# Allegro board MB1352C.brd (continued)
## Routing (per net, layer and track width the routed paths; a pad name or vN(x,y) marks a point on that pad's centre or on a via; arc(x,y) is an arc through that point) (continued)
VBUS1: length 21.2
  TOP w0.254: CN7.B4 9.38,15.18 CN7.A9 ; CN7.B9 9.38,17.68 CN7.A4
  TOP w0.356: 21.08,6.99 22.1,5.97 U23.5
  TOP w0.508: R69.2 19.56,10.59 ; R69.2 18.24,8.64 ; R69.2 20.88,8.64 ; R69.2 19.56,6.68 ; 16.38,13.08 v1(17.53,13.08)
  BOTTOM w0.508: v1(18.67,17.4) 20.45,17.4 22.1,19.05 R64.2 ; D6.1 v1(4.19,14.61) ; C16.2 10.67,14.35 9.89,15.13 9.43,15.13 CN7.B4
  vias: v1(17.65,10.67) v1(17.65,9.93) v1(17.65,9.12) v1(17.65,8.26)
VBUS2: length 38.1
  TOP w0.254: CN5.B4 104.92,43.24 CN5.A9 ; CN5.B9 104.92,40.74 CN5.A4
  TOP w0.356: U24.5 44.32,11.94 43.94,12.32 43.31,12.32
  TOP w0.508: 40.33,14.48 R70.2 ; R70.2 41.66,12.52 ; R70.2 42.98,14.48 ; R70.2 41.66,16.43
  L3_SIG w0.508: CN5.B9 104.62,40.79 104.22,40.38 104.22,37.13 104.85,36.5 108.58,36.5 109.22,37.13 109.22,38.94 v1(109.42,39.14)
  BOTTOM w0.508: CN5.B9 104.5,40.79 104.19,41.09 104.19,42.83 104.55,43.19 CN5.B4 ; v1(109.42,39.14) 109.73,39.45 C15.2 D1.1 ; v1(43.03,16.89) 46.86,16.89 50.04,20.07 R63.2
  vias: v1(40.65,16.93) v1(41.42,16.89) v1(42.29,16.89)
VDD: length 105.8
  TOP w0.165: v1(28.45,41.02) 27.69,40.26 U13.1 ; v1(25.4,41.91) 25.4,41.15 25.69,40.86 U13.6
  TOP w0.203: U13.28 27.69,34.03 28.27,33.45 v1(28.52,33.45) ; C51.2 18.2,24.17 U17.10 ; C47.2 95.72,54.19 U16.10 ; v1(23.88,33.53) 24.39,34.04 U13.20
  TOP w0.254: U6.22 v2(66.52,47.24) ; U6.25 v2(65.02,47.24) ; U6.10 66.52,40.89 v2(66.71,40.7) ; U6.13 68.71,42.57 68.96,42.31 68.96,42.16 v1(69.09,42.04) ; U6.26 64.52,47.63 v2(64.9,48.01) ; U6.29 v2(63.02,47.24) ; v1(69.22,45.85) 68.94,45.57 U6.19 ; U6.6 v2(64.52,40.89) ; v3(81.81,41.15) 81.86,41.1 81.86,40.72 U8.H3 ; v2(62.74,40.51) 63.02,40.79 U6.3 ; U8.E4 82.83,42.16 v3(82.89,42.23) ; v2(64.77,40.13) 65.02,40.38 U6.7 ; U8.E3 v3(81.41,42.16) ; U6.32 61.11,45.57 60.71,45.97 ; U6.38 61.09,42.32 61.09,41.53 60.58,41.02 v1(60.33,41.02) ; U8.B2 v3(81.42,43.18)
  TOP w0.508: R8.1 v1(94.74,31.88) ; R24.1 R22.1 v1(56.13,43.05) ; v1(58.67,48.13) C17.1 59.56,47.12 60.71,45.97 ; R21.1 v1(33.05,43.31) ; v1(56.13,44.32) R17.1 R13.1 ; v1(71.63,36.7) 71.63,37.85 C35.1 70.87,37.85 v1(70.87,36.7) ; R28.1 v1(83.31,33.78) ; R51.2 94.23,18.29 v1(94.97,18.29) ; C47.2 96.08,53.4 v1(96.58,53.4) ; v1(19.81,24.77) C51.2
  BOTTOM w0.381: C89.1 81.66,40.77 81.81,40.92 v3(81.81,41.15) ; C80.1 81.42,43.7 v3(81.42,43.18) ; C81.1 80.52,42.16 v3(81.41,42.16) ; C87.1 83.38,42.23 v3(82.89,42.23)
  BOTTOM w0.508: v2(62.74,40.51) 62.48,40.77 C86.1 ; C91.1 25.27,41.78 v1(25.4,41.91) ; v1(73.64,44.05) 72.92,44.05 72.64,44.32 R88.1 R91.1 ; C77.1 65.91,46.35 v2(65.02,47.24) ; v1(93.47,29.34) 93.47,29.97 R9.2 ; v1(28.52,33.45) 28.5,33.45 27.94,34.01 C93.1 ; v1(76.33,43.18) 75.95,43.56 R87.1 ; v2(64.9,48.01) 64.01,47.12 64.01,46.23 63.63,45.85 C78.1 ; C47.2 96.08,53.4 v1(96.58,53.4) ; v1(76.96,36.32) 76.96,37.34 C92.1 75.95,37.34 v1(75.95,36.32) ; v1(69.09,42.04) 69.34,41.78 C82.1 ; 98.3,3.94 CN8.18 ; CN8.18 97.41,4.83 ; CN8.18 98.3,5.72 ; CN8.18 99.19,4.83 ; C75.1 70.48,45.97 69.34,45.97 v1(69.22,45.85) ; C90.1 28.45,40.39 v1(28.45,41.02) ; C83.1 66.9,40.89 v2(66.71,40.7) ; C102.1 96.09,3.68 ; C102.1 95.5,4.31 ; C102.1 94.92,3.68 ; R106.2 v1(81.92,33.78) ; CN9.18 C101.1 v1(39.24,5.84) ; C76.1 68.07,45.69 v2(66.52,47.24) ; C84.1 65.53,40.89 v2(64.77,40.13) ; v2(63.02,47.24) 61.34,45.57 C79.1 ; C88.1 59.44,40.51 59.94,41.02 v1(60.33,41.02) ; R103.1 20.32,36.83 v1(19.68,37.47) 20.32,38.1 R100.1 ; v1(32.26,34.54) 32.18,34.62 32.18,35.38 R108.1 ; C95.1 v1(23.62,32.38) ; v1(19.81,24.77) C51.2 ; R28.1 v1(83.31,33.78) ; v1(30.04,45.66) R90.1 ; R107.2 v1(80.52,33.78) ; v1(23.88,33.53) 22.61,33.53 C94.1 ; C85.1 v2(64.52,40.89) ; R97.1 v1(32.89,40.26) ; R93.1 v1(21.34,42.67)
  vias: v1(89.66,13.59) v1(89.66,12.7) v1(90.55,13.59) v1(90.55,12.7)
1_CC1: length 137.7
  TOP w0.127: SB4.2 87.63,39.75 87.63,38.31 T2.3 v1(87.16,36.62) ; SB21.2 v1(15.75,29.46)
  L3_SIG w0.102: v1(87.16,36.62) 86.66,36.62 86.11,36.07 86.11,32.4 v1(85.09,31.38)
  BOTTOM w0.127: v1(87.16,36.62) 86.7,36.62 84.84,38.48 84.84,45.21 79.76,50.29 48.9,50.29 46.23,47.62 46.23,36.6 42.55,32.92 39.64,32.92 38.45,31.72 34.89,31.72 33.53,30.36 33.53,29.46 32.77,28.7 30.35,28.7 29.08,27.43 20.24,27.43 17.48,30.2 16.48,30.2 v1(15.75,29.46) 16.26,28.96 16.26,25.4 16,25.15 14.99,25.15 14.1,24.26 14.1,20.04 15.75,18.38 15.75,15.11 SB56.2 ; T12.3 86.36,27.56 85.09,28.83 v1(85.09,31.38) 85.12,31.38 D11.2
1_CC2: length 137.8
  TOP w0.127: SB22.2 v1(17.27,29.59) ; T4.3 87.38,27.56 v1(86.11,28.83) 85.98,28.96 D12.2 ; v1(90.81,36.58) 90.81,37.55 T3.3 91.1,40.05 SB5.2
  L3_SIG w0.102: v1(86.11,28.83) 86.61,29.34 86.61,35.69 87,36.07 90.3,36.07 v1(90.81,36.58)
  BOTTOM w0.127: SB57.2 16.32,18.22 16.32,18.35 14.48,20.19 14.48,24 15.11,24.64 16.13,24.64 16.76,25.27 16.76,29.08 v1(17.27,29.59) 17.55,29.59 20.09,27.05 29.34,27.05 30.61,28.32 33.02,28.32 34.04,29.34 34.04,30.33 35.05,31.34 38.61,31.34 39.78,32.51 42.8,32.51 46.74,36.45 46.74,47.37 49.15,49.78 79.63,49.78 84.33,45.09 84.33,38.23 86.49,36.07 90.3,36.07 v1(90.81,36.58)
1_SBU1: length 38.6
  TOP w0.127: v1(13.97,25.02) 14.95,25.02 15.07,24.89 U17.15 ; U13.27 27.29,33.93 29.08,32.13 29.34,32.13 R39.2 29.34,30.86 29.34,28.98 v1(28.7,28.35)
  L3_SIG w0.102: v1(28.7,28.35) 27.53,27.18 22.23,27.18 20.45,25.4 19.43,25.4 18.67,24.64 15.37,24.64 14.73,25.27 14.22,25.27 v1(13.97,25.02) 13.97,24.51 14.35,24.13 14.35,22.61 16,20.95 16,20.09 15.89,19.97 15.89,15.89 v1(14.73,14.73)
  BOTTOM w0.127: SB58.2 13.72,14.73 v1(14.73,14.73)
1_SBU2: length 35.9
  TOP w0.127: U13.26 26.89,33.69 28.16,32.42 28.16,32.02 28.69,31.5 R38.2 28.07,30.86 28.07,28.85 v1(27.69,28.47) ; v1(13.97,25.78) 14.99,25.78 15.47,25.29 U17.14
  L3_SIG w0.102: v1(14.99,17.65) 15.49,18.16 15.49,20.95 13.08,23.37 13.08,24.89 v1(13.97,25.78) 14.86,25.78 15.6,25.04 18.57,25.04 19.3,25.78 20.19,25.78 22.04,27.63 26.84,27.63 v1(27.69,28.47)
  BOTTOM w0.127: SB53.2 v1(14.99,17.65)
2_SBU1: length 27.9
  TOP w0.127: U16.15 99.86,52.88 100.97,51.77 v1(100.97,51.44) 102.36,50.04 SB41.2 ; U8.A5 82.92,44.31 83.82,45.21 83.82,46.1 83.83,46.11 83.83,47.41 84.55,48.13 85.34,48.13 v2(85.47,48.26)
  L3_SIG w0.102: v1(100.97,51.44) 100.84,51.31 99.69,51.31 98.3,49.91 97.03,49.91 96.01,48.9 86.11,48.9 v2(85.47,48.26)
2_SBU2: length 27
  TOP w0.127: U8.A6 84.21,44.95 84.21,47.25 84.71,47.75 85.34,47.75 v2(85.47,47.62) ; U16.14 99.46,52.74 100.33,51.87 100.33,51.31 v1(100.97,50.67) SB42.2
  L3_SIG w0.102: v1(100.97,50.67) 100.71,50.93 99.82,50.93 98.42,49.53 97.16,49.53 96.14,48.51 86.36,48.51 v2(85.47,47.62)
A0: length 4.1
  TOP w0.127: U6.33 60.72,45.07 60.07,45.72 v1(59.69,45.72) 58.8,45.72 R13.2
  BOTTOM w0.127: v1(59.69,45.72) 58.8,45.72 R13.2
A1: length 4.4
  TOP w0.127: R17.2 59.3,44.95 v1(59.69,44.95) 60.21,44.95 60.59,44.57 U6.34
  BOTTOM w0.127: v1(59.69,44.95) 59.3,44.95 R17.2
A2: length 4.1
  TOP w0.127: U6.35 60.58,44.07 59.94,43.43 v1(59.56,43.43) 59.05,43.43 R22.2
  BOTTOM w0.127: R22.2 59.05,43.43 v1(59.56,43.43)
ADDR1: length 6.7
  TOP w0.127: U8.H5 v3(82.92,41.12)
  BOTTOM w0.127: v3(82.92,41.12) 82.92,36.71 R105.2 R104.1
ADDR2: length 9.6
  TOP w0.127: v3(82.96,42.77) 82.85,42.66 U8.D4
  BOTTOM w0.127: R87.2 R86.1 79.76,45.59 80.9,44.45 80.9,43.05 81.18,42.77 v3(82.96,42.77)
AUX_N_1: length 14.7
  TOP w0.13: R12.2 20.13,46.8 19.67,46.8 v2(19.51,46.96) ; U9.1 17.13,41.33 16.65,41.33 v2(16.48,41.49) 16.32,41.33 15.65,41.33 15.16,40.84 14.81,40.84 14.55,41.1 CN6.17
  BOTTOM w0.13: v2(16.48,41.49) 16.65,41.33 16.94,41.33 17.5,41.88 17.5,45.67 18.63,46.8 19.34,46.8 v2(19.51,46.96) 19.67,46.8 20.13,46.8 R12.2
AUX_N_2: length 15.3
  TOP w0.13: v2(68.88,57.56) 68.72,57.72 68.72,58.86 69.04,59.18 CN2.17 ; C14.2 71,51.05 71,52.87 70.49,53.38 70.49,53.91 v2(70.66,54.08) 70.49,54.24 U3.2
  BOTTOM w0.13: R31.1 68.71,59.05 68.71,57.74 v2(68.88,57.56) 68.72,57.39 68.72,56.63 70.49,54.86 70.49,54.24 v2(70.66,54.08)
AUX_P_1: length 14.8
  TOP w0.13: CN6.15 14.52,40.1 14.88,40.46 15.32,40.46 15.81,40.95 16.32,40.95 v2(16.48,40.78) 16.65,40.95 17.13,40.95 U9.2 ; v2(19.51,46.25) 19.67,46.42 20.13,46.42 R11.2
  BOTTOM w0.13: v2(16.48,40.78) 16.65,40.95 17.1,40.95 17.88,41.73 17.88,45.52 18.78,46.42 19.34,46.42 v2(19.51,46.25) 19.67,46.42 20.13,46.42 R11.2
AUX_P_2: length 15.3
  TOP w0.13: CN2.15 68.04,59.17 68.34,58.87 68.34,57.72 v2(68.17,57.56) ; U3.1 69.99,54.99 70.11,54.87 70.11,54.24 v2(69.95,54.08) 70.11,53.91 70.11,53.22 70.62,52.72 70.62,50.93 C13.2
  BOTTOM w0.13: v2(69.95,54.08) 70.11,54.24 70.11,54.7 68.34,56.47 68.34,57.39 v2(68.17,57.56) 68.33,57.71 68.33,59.05 R30.1
C1_CC1: length 32.1
  TOP w0.127: CN7.A5 11.08,17.18 11.3,17.4 v1(14.22,17.4) ; D5.6 16.8,16.57 16.92,16.44 17.33,16.44 v1(17.65,16.76) 17.79,16.9 17.79,17.76 18.03,18 18.03,18.65 17.53,19.16 v1(17.44,19.16) 17.02,19.58 17.02,20.67 16.28,21.41 U17.4
  L3_SIG w0.102: v1(14.73,13.97) 14.22,14.48 v1(14.22,17.4)
  BOTTOM w0.127: 16.51,13 18.16,14.65 18.16,16.26 v1(17.65,16.76) ; v1(14.73,13.97) 15.37,13.97 SB56.1 ; C112.2 16.83,19.11 17.46,19.11 17.51,19.16 v1(17.44,19.16) 17.93,18.67 19.43,18.67 21.72,20.95 21.72,22.35 SB54.1
C1_CC2: length 33.5
  TOP w0.127: CN7.B5 8.14,15.63 7.62,15.11 7.62,13.59 8.13,13.08 8.89,13.08 10.54,11.43 11.05,11.43 11.81,10.67 15.37,10.67 15.62,10.92 15.62,13.85 15.93,14.16 D5.4 17.47,14.67 v1(17.53,14.73) 18.17,15.38 18.17,17.6 18.41,17.85 18.41,19.05 v1(18.16,19.3) 17.4,20.07 17.4,20.83 16.68,21.55 U17.5
  BOTTOM w0.127: v1(17.53,14.73) 17.53,14.99 17.02,15.49 17.02,16 SB57.1 ; C113.2 17.4,20.07 v1(18.16,19.3) 19.43,19.3 20.95,20.83 SB55.1
C1_D+: length 88.2
  TOP w0.155: CN7.A6 11.47,16.68 v1(11.56,16.76) ; v1(7.47,24.73) 7.61,24.59 10.08,24.59 SB71.1
  L3_SIG w0.13: v1(7.47,24.73) 7.25,24.51 7.02,24.51 6.81,24.72 6.81,25.44 7.04,25.67 7.04,25.93 6.81,26.16 6.81,26.42 7.04,26.65 7.04,26.91 6.81,27.13 6.81,27.39 7.04,27.62 7.04,27.88 6.81,28.11 6.81,28.37 7.04,28.6 7.04,28.86 6.81,29.08 6.81,38.81 14.33,46.33 14.33,47.57 16.46,49.71 31.46,49.71 31.66,49.5 31.92,49.5 32.12,49.71 32.38,49.71 32.58,49.5 32.84,49.5 33.05,49.71 33.3,49.71 33.51,49.5 33.77,49.5 33.97,49.71 37.64,49.71 39.23,48.12 39.23,47.84 39.41,47.66 39.68,47.66 39.87,47.48 39.87,47.2 40.05,47.02 40.32,47.02 40.51,46.84 40.51,46.56 40.69,46.38 40.96,46.38 41.15,46.2 41.15,45.92 41.33,45.74 41.6,45.74 41.97,45.37 41.97,41.79 41.84,41.66 v1(41.38,41.66)
  BOTTOM w0.155: v1(7.47,24.73) 7.25,24.51 5.69,24.51 5,23.83 5,17.42 6.17,16.26 8.89,16.26 9.12,16.03 CN7.B6 10.19,16.89 10.41,16.89 10.52,16.79 10.52,16 10.67,15.85 10.89,15.85 11.02,15.98 11.02,16.61 11.18,16.76 v1(11.56,16.76) ; SB63.2 v1(41.38,41.66) SB61.2
C1_D-: length 88.4
  TOP w0.155: SB70.1 10.06,24.21 7.76,24.21 v1(7.47,23.91) ; v1(12.32,16.76) 12.32,16.64 11.86,16.18 CN7.A7
  L3_SIG w0.13: v1(42.95,41.66) 42.48,41.66 42.35,41.79 42.35,45.53 37.8,50.09 16.3,50.09 13.94,47.73 13.94,46.49 6.43,38.97 6.43,24.56 6.86,24.13 7.25,24.13 v1(7.47,23.91)
  BOTTOM w0.155: SB62.2 v1(42.95,41.66) SB60.2 ; v1(7.47,23.91) 7.25,24.13 5.85,24.13 5.38,23.67 5.38,23.31 5.64,23.06 5.64,22.75 5.38,22.49 5.38,22.18 5.64,21.93 5.64,21.62 5.38,21.37 5.38,21.06 5.64,20.8 5.64,20.49 5.38,20.24 5.38,19.93 5.64,19.67 5.64,19.36 5.38,19.11 5.38,18.8 5.64,18.55 5.64,18.24 5.38,17.98 5.38,17.58 6.32,16.64 6.66,16.64 6.84,16.81 7.15,16.81 7.33,16.64 9.14,16.64 CN7.B7 9.59,16.83 10.04,17.27 11.77,17.27 11.77,17.27 11.81,17.27 v1(12.32,16.76)
C1_RX1+: length 58.7
  TOP w0.155: v2(12.35,18.68) 12.51,18.52 13.09,18.52 U19.4 ; v2(31.36,33.11) 31.19,33.27 30.1,33.27 28.78,34.59 28.78,35.12 28.48,35.42 28.2,35.42 U13.30
  L3_SIG w0.13: v2(12.35,18.68) 12.54,18.49 13.02,18.49 13.34,18.8 13.34,20.29 10.69,22.93 10.69,25 13,27.3 18.59,27.3 22.88,31.6 24.49,31.6 24.72,31.83 24.98,31.83 25.2,31.6 25.46,31.6 25.69,31.83 25.95,31.83 26.18,31.6 26.44,31.6 26.67,31.83 26.93,31.83 27.16,31.6 27.41,31.6 27.64,31.83 27.9,31.83 28.13,31.6 28.39,31.6 28.62,31.83 28.88,31.83 29.11,31.6 29.37,31.6 29.59,31.83 29.85,31.83 30.08,31.6 30.34,31.6 30.57,31.83 30.83,31.83 31.06,31.6 31.72,31.6 32.03,31.9 32.03,33.09 31.85,33.27 31.52,33.27 v2(31.36,33.11)
  BOTTOM w0.155: CN7.B11 8.22,18.41 8.05,18.41 7.92,18.54 7.92,19 7.77,19.15 7.47,19.15 7.34,19.02 7.34,18.59 7.16,18.41 6.89,18.41 6.73,18.57 6.73,19.38 6.91,19.55 6.91,19.86 6.73,20.04 6.73,20.35 6.91,20.53 6.91,20.84 6.73,21.02 6.73,21.34 7.49,22.1 7.93,22.1 8.1,21.92 8.41,21.92 8.59,22.1 8.9,22.1 9.08,21.92 9.39,21.92 9.57,22.1 9.88,22.1 10.05,21.92 10.36,21.92 10.54,22.1 10.85,22.1 11.03,21.92 11.34,21.92 11.52,22.1 11.91,22.1 12.16,21.84 12.16,21.64 12.42,21.39 12.62,21.39 13.07,20.94 13.07,19.73 12.99,19.65 12.98,19.65 12.9,19.57 12.9,19.26 12.98,19.18 12.99,19.18 13.07,19.09 13.07,18.81 12.75,18.49 12.54,18.49 v2(12.35,18.68)
C1_RX1-: length 58.7
  TOP w0.155: v2(12.35,17.97) 12.51,18.13 13.09,18.13 U19.5 ; v2(31.36,33.82) 31.19,33.66 30.26,33.66 29.16,34.75 29.16,35.28 28.63,35.8 28.2,35.8 U13.31
  L3_SIG w0.13: v2(12.35,17.97) 12.49,18.11 13.18,18.11 13.72,18.64 13.72,20.45 11.07,23.09 11.07,24.84 13.16,26.92 18.75,26.92 23.04,31.22 31.88,31.22 32.41,31.74 32.41,33.25 32,33.66 31.52,33.66 v2(31.36,33.82)
  BOTTOM w0.155: v2(12.35,17.97) 12.49,18.11 12.9,18.11 13.45,18.65 13.45,21.1 12.06,22.48 7.34,22.48 6.35,21.49 6.35,18.41 6.74,18.03 CN7.B10
C1_RX2+: length 55.2
  TOP w0.155: CN7.A11 10.6,14.25 11.25,14.25 11.43,14.07 11.43,13.34 11.86,12.9 12.18,12.9 v2(12.35,12.74) 12.51,12.9 12.9,12.9 12.96,12.84 U20.2 ; v2(30.72,41.57) 30.56,41.4 29.72,41.4 28.57,40.26 28.57,39.62 28.36,39.41 U13.40
  L3_SIG w0.13: v2(12.35,12.74) 12.51,12.9 15.32,12.9 16.89,14.48 16.89,19.56 17.27,19.94 18.54,19.94 19.94,21.34 19.94,22.1 22.96,25.12 31.88,25.12 34.09,27.33 34.09,36.94 33.28,37.74 32.74,37.74 32.13,38.35 32.13,40.91 31.63,41.4 30.89,41.4 v2(30.72,41.57)
C1_RX2-: length 55.2
  TOP w0.155: U13.39 28.2,39.01 28.22,39.03 28.52,39.03 28.96,39.47 28.96,40.1 29.88,41.02 30.57,41.02 30.72,40.87 v2(30.72,40.86) ; CN7.A10 10.58,14.63 11.41,14.63 11.81,14.22 11.81,13.49 12.02,13.28 12.18,13.28 v2(12.35,13.45) 12.51,13.28 12.8,13.28 12.86,13.34 U20.1
  L3_SIG w0.13: v2(30.72,40.86) 30.89,41.02 31.48,41.02 31.75,40.75 31.75,38.2 32.59,37.36 33.12,37.36 33.71,36.78 33.71,34.46 33.53,34.29 33.53,34.03 33.71,33.85 33.71,33.59 33.53,33.41 33.53,33.15 33.71,32.98 33.71,32.72 33.53,32.54 33.53,32.28 33.71,32.1 33.71,31.84 33.53,31.67 33.53,31.41 33.71,31.23 33.71,27.49 31.72,25.5 31.03,25.5 30.82,25.7 30.56,25.7 30.36,25.5 30.1,25.5 29.9,25.7 29.64,25.7 29.44,25.5 29.18,25.5 28.97,25.7 28.71,25.7 28.51,25.5 28.25,25.5 28.05,25.7 27.79,25.7 27.59,25.5 22.8,25.5 19.56,22.26 19.56,21.49 18.38,20.32 17.11,20.32 16.51,19.72 16.51,14.64 15.16,13.28 12.51,13.28 v2(12.35,13.45)
C1_SBU1: length 15.7
  TOP w0.127: v1(13.59,21.84) 13.72,21.84 13.74,21.87 U17.1 ; CN7.A8 11.27,15.68 12.41,14.54 v1(12.43,14.54) 13.41,14.54 D5.3
  L3_SIG w0.102: v1(12.43,14.54) 13.72,15.83 13.72,17.65 14.35,18.29 14.35,21.46 13.97,21.84 v1(13.59,21.84)
  BOTTOM w0.127: v1(12.43,14.54) 12.43,14.24 13.46,13.21 SB58.1
C1_SBU2: length 19.6
  TOP w0.127: v1(12.32,15.62) 12.32,15.72 13.17,16.57 D5.1 14.54,16.57 14.99,17.02 15.11,17.02 15.49,17.4 15.49,21.85 U17.2
  L3_SIG w0.102: v1(12.32,15.62) 12.08,15.38 10.67,13.97 10.67,13.59 10.16,13.08 8.38,13.08 7.87,13.59 7.87,16.47 CN7.B8
  BOTTOM w0.127: SB53.1 13.08,16 12.7,15.62 v1(12.32,15.62)
C1_TX1+: length 42.4
  TOP w0.155: C43.2 32.45,36 32.82,36 v2(32.98,35.84) ; U19.1 12.86,20.08 12.8,20.02 12.51,20.02 v2(12.35,20.18) 12.18,20.02 11.76,20.02 11.43,19.68 11.43,18.95 11.1,18.62 10.59,18.62 CN7.A2
  L3_SIG w0.13: v2(12.35,20.18) 12.18,20.02 10.85,20.02 9.12,21.74 9.12,22.32 9.35,22.55 9.35,22.84 9.12,23.07 9.12,23.36 9.35,23.59 9.35,23.88 9.12,24.1 9.12,24.39 9.35,24.62 9.35,24.91 9.12,25.14 9.12,25.5 9.41,25.78 9.73,25.78 9.91,25.97 9.91,26.29 10.1,26.47 10.42,26.47 10.6,26.66 10.6,26.98 10.79,27.16 11.11,27.16 11.29,27.35 11.29,27.67 11.82,28.19 12.54,28.19 12.74,27.99 13,27.99 13.21,28.19 17.78,28.19 23.75,34.16 28.73,34.16 30.57,36 32.82,36 v2(32.98,35.84)
C1_TX1-: length 42.4
  TOP w0.155: CN7.A3 10.59,18.24 11.25,18.24 11.81,18.8 11.81,19.53 11.92,19.64 12.18,19.64 v2(12.35,19.47) 12.51,19.63 12.9,19.63 12.96,19.58 U19.2 ; v2(32.98,36.55) 32.82,36.39 32.45,36.39 C40.2
  L3_SIG w0.13: v2(12.35,19.47) 12.18,19.63 10.69,19.63 8.74,21.58 8.74,25.65 11.66,28.57 17.62,28.57 23.59,34.54 28.57,34.54 30.42,36.39 32.82,36.39 v2(32.98,36.55)
C1_TX2+: length 65.1
  TOP w0.155: C26.2 32.45,38.93 33.33,38.93 v2(33.49,39.09) ; U20.5 12.96,11.34 12.9,11.4 12.51,11.4 v2(12.35,11.24)
  L3_SIG w0.13: v2(12.35,11.24) 12.51,11.4 17.4,11.4 18.8,12.8 18.8,15.34 19.56,16.1 19.56,19.27 20.86,20.57 23.78,20.57 26.57,23.37 32.26,23.37 35.36,26.47 35.36,37.92 34.37,38.91 33.67,38.91 v2(33.49,39.09)
  BOTTOM w0.155: v2(12.35,11.24) 12.68,11.57 12.84,11.57 13.06,11.35 13.06,10.8 12.67,10.41 12.06,10.41 11.35,11.13 10.95,11.13 10.75,11.33 10.44,11.33 10.23,11.13 9.92,11.13 9.72,11.33 9.41,11.33 9.21,11.13 8.9,11.13 8.69,11.33 8.38,11.33 8.18,11.13 7.87,11.13 7.67,11.33 7.36,11.33 7.15,11.13 6.78,11.13 6.45,11.46 6.45,11.97 6.68,12.2 6.68,12.51 6.45,12.74 6.45,13.05 6.68,13.28 6.68,13.59 6.45,13.82 6.45,14.15 6.75,14.45 7.07,14.45 7.17,14.35 7.24,14.27 7.24,13.86 7.39,13.72 7.59,13.72 7.72,13.84 7.72,14.27 7.9,14.45 8.21,14.45 CN7.B2
C1_TX2-: length 65.2
  TOP w0.155: C37.2 32.45,38.54 33.33,38.54 v2(33.49,38.38) ; v2(12.35,11.95) 12.51,11.78 12.8,11.78 12.86,11.84 U20.4
  L3_SIG w0.13: v2(33.49,38.38) 33.64,38.53 34.21,38.53 34.98,37.76 34.98,36.93 34.8,36.75 34.8,36.49 34.98,36.32 34.98,36.06 34.8,35.88 34.8,35.62 34.98,35.44 34.98,35.18 34.8,35.01 34.8,34.75 34.98,34.57 34.98,34.31 34.8,34.13 34.8,33.87 34.98,33.7 34.98,26.62 32.1,23.75 31.31,23.75 31.11,23.95 30.85,23.95 30.65,23.75 30.39,23.75 30.18,23.95 29.92,23.95 29.72,23.75 29.46,23.75 29.26,23.95 29,23.95 28.8,23.75 28.54,23.75 28.33,23.95 28.08,23.95 27.87,23.75 26.42,23.75 23.62,20.95 20.7,20.95 19.18,19.43 19.18,16.26 18.41,15.49 18.41,12.95 17.25,11.78 12.51,11.78 v2(12.35,11.95)
  BOTTOM w0.155: CN7.B3 6.59,14.83 6.07,14.31 6.07,11.3 6.62,10.74 11.2,10.74 11.91,10.03 12.83,10.03 13.44,10.64 13.44,11.51 13,11.95 v2(12.35,11.95)
C2_CC1: length 35.5
  TOP w0.127: CN5.A5 103.26,41.24 103.07,41.05 102.21,41.05 101.73,41.53 v1(100.2,41.53) 99.39,42.34 v1(99.39,43.3) ; U16.4 98.66,57.89 v1(99.31,58.55)
  L3_SIG w0.102: v1(99.31,58.55) 98.3,57.53 93.97,57.53 v1(93.07,56.63)
  BOTTOM w0.127: v1(99.31,58.55) 99.57,58.55 100.46,57.66 100.46,54.18 99.09,52.81 99.09,50.04 98.93,49.89 98.93,49.17 100.78,47.33 D2.6 100.78,45.53 SB44.1 99.39,44.15 v1(99.39,43.3) ; v1(93.07,56.63) 93.95,55.75 SB50.1 ; v1(100.2,41.53) C110.2
C2_CC2: length 45
  TOP w0.127: U16.5 98.26,58.46 v1(98.45,58.65)
  L3_SIG w0.102: v1(98.45,58.65) 97.71,57.91 93.43,57.91 v1(93.09,58.25) ; CN5.B5 107.31,41.15 v1(107.57,41.15) 107.57,47.24 106.98,47.83 105.23,47.83 104.72,48.34 v1(104.14,48.34) 103.68,47.88 101.09,47.88 v1(99.57,49.4)
  BOTTOM w0.127: SB45.1 101.85,45.72 102.68,46.54 D2.4 102.68,47.43 103.06,47.82 103.43,47.82 103.95,48.34 v1(104.14,48.34) ; C111.2 v1(107.57,41.15) ; v1(93.09,58.25) 93.94,57.4 SB49.1 ; v1(99.57,49.4) 99.49,49.48 99.49,52.63 100.84,53.98 100.84,57.91 99.54,59.21 99.01,59.21 v1(98.45,58.65)
C2_D+: length 60.5
  TOP w0.155: v2(102.08,42.39) 102.08,42.27 102.57,41.78 103.72,41.78 CN5.A6 ; SB65.1 v1(88.24,52.22) SB67.1 ; SB69.1 104.11,55.4 104.47,55.4 104.85,55.78 104.85,57.33 105.25,57.73 105.58,57.73 v2(105.75,57.56)
  L3_SIG w0.13: v1(88.24,52.22) 88.24,51.63 88.11,51.5 87.72,51.5 87.5,51.72 87.5,53.06 87.79,53.34 88.41,53.34 88.64,53.11 88.9,53.11 89.13,53.34 89.39,53.34 89.62,53.11 89.88,53.11 90.1,53.34 90.36,53.34 90.59,53.11 90.85,53.11 91.08,53.34 91.34,53.34 91.57,53.11 91.83,53.11 92.06,53.34 92.31,53.34 92.54,53.11 92.8,53.11 93.03,53.34 94.08,53.34 95.47,51.94 97.82,51.94 98.84,52.96 100.13,52.96 104.9,57.73 105.58,57.73 v2(105.75,57.56) ; CN5.B6 104.91,42.39 104.27,43.03 102.79,43.03 102.62,42.85 102.54,42.85 v2(102.08,42.39)
  BOTTOM w0.155: v2(105.75,57.56) 105.91,57.73 106.3,57.73 106.55,57.47 106.55,57.03 106.35,56.83 106.05,56.83 105.83,56.61 105.83,56.31 105.62,56.09 105.32,56.09 105.1,55.87 105.1,55.57 104.88,55.35 104.58,55.35 104.36,55.13 104.36,54.84 103.96,54.44 103.96,50.6 106.2,48.36 107.19,48.36 108.53,47.02 108.53,46.73 108.33,46.53 108.33,46.22 108.53,46.02 108.53,45.71 108.33,45.5 108.33,45.19 108.53,44.99 108.53,44.3 107.82,43.59 107.55,43.59 107.33,43.37 107.33,43.1 107.11,42.88 106.84,42.88 106.62,42.66 106.62,42.39 106.4,42.16 105.19,42.16 CN5.B6
C2_D-: length 60.4
  TOP w0.155: SB66.1 v1(88.24,50.65) 89.28,50.65 ; CN5.A7 103.7,42.16 102.97,42.16 v2(102.74,42.39) ; v2(105.75,58.27) 105.58,58.11 105.09,58.11 104.47,57.49 104.47,55.94 104.31,55.78 104.11,55.78 SB68.1
  L3_SIG w0.13: CN5.B7 104.44,42.11 104.44,42.32 104.11,42.65 103.91,42.65 103.78,42.52 103.78,42.01 103.68,41.91 103.48,41.91 103.35,42.04 103.35,42.52 103.23,42.65 102.95,42.65 102.77,42.47 102.77,42.42 v2(102.74,42.39) ; v2(105.75,58.27) 105.58,58.11 104.74,58.11 99.97,53.34 98.68,53.34 97.66,52.32 95.63,52.32 94.23,53.72 87.63,53.72 87.12,53.21 87.12,51.56 87.57,51.12 88.07,51.12 88.24,50.95 v1(88.24,50.65)
  BOTTOM w0.155: v2(105.75,58.27) 105.91,58.11 106.46,58.11 106.93,57.63 106.93,56.87 104.34,54.28 104.34,50.75 106.36,48.74 107.35,48.74 108.92,47.17 108.92,44.15 106.55,41.78 105.17,41.78 CN5.B7
C2_RX1+: length 40.8
  TOP w0.155: v2(86.2,39.79) 86.03,39.62 85.12,39.62 84.14,40.6 83.48,40.6 U8.H6 ; U11.1 101.99,38.3 102.52,38.3 v2(102.74,38.08)
  L3_SIG w0.13: v2(102.74,38.08) 102.53,38.3 101.32,38.3 99.45,36.42 95.53,36.42 94.39,37.57 85.57,37.57 85.06,38.07 85.06,39.22 85.47,39.62 86.03,39.62 v2(86.2,39.79)
  BOTTOM w0.155: CN5.B11 105.88,39.8 107.14,39.8 107.62,39.32 107.62,39.03 107.44,38.85 107.44,38.54 107.62,38.37 107.62,37.17 107.26,36.8 105.67,36.8 105.46,37.01 105.15,37.01 104.95,36.8 104.64,36.8 104.37,37.08 104.37,37.69 104.22,37.85 103.86,37.85 103.71,37.69 103.71,36.93 103.58,36.8 103.18,36.8 102.98,37.01 102.67,37.01 102.47,36.8 102.18,36.8 101.96,37.03 101.96,38.27 102.19,38.51 102.46,38.51 102.74,38.23 v2(102.74,38.08)
C2_RX1-: length 40.8
  TOP w0.155: v2(86.2,39.08) 86.03,39.24 84.96,39.24 83.98,40.22 83.48,40.22 U8.J6 ; U11.2 101.99,38.68 102.53,38.68 v2(102.74,38.89)
  L3_SIG w0.13: v2(86.2,39.08) 86.03,39.24 85.63,39.24 85.45,39.06 85.45,38.23 85.73,37.95 86.23,37.95 86.43,38.15 86.69,38.15 86.89,37.95 87.15,37.95 87.35,38.15 87.61,38.15 87.82,37.95 88.08,37.95 88.28,38.15 88.54,38.15 88.74,37.95 89,37.95 89.2,38.15 89.46,38.15 89.67,37.95 89.92,37.95 90.13,38.15 90.39,38.15 90.59,37.95 90.85,37.95 91.05,38.15 91.31,38.15 91.51,37.95 91.77,37.95 91.98,38.15 92.24,38.15 92.44,37.95 94.54,37.95 95.69,36.8 99.29,36.8 101.16,38.68 102.53,38.68 v2(102.74,38.89)
  BOTTOM w0.155: v2(102.74,38.89) 102.04,38.89 101.57,38.43 101.57,36.88 102.03,36.42 107.42,36.42 108,37.01 108,39.48 107.3,40.18 105.88,40.18 CN5.B10
C2_RX2+: length 22.6
  TOP w0.155: 102.01,44.18 101.99,44.18 101.98,44.2 ; 102.01,44.18 102.58,44.18 v2(102.79,44.39) 103.01,44.18 103.36,44.18 103.42,44.24 CN5.A11 ; 102.01,44.18 101.98,44.2 ; 101.98,44.2 U5.2 ; U8.D6 83.48,42.6 84.77,42.6 85.22,43.05 85.65,43.05 v2(85.81,43.22)
  L3_SIG w0.13: v2(102.79,44.39) 102.58,44.18 99.1,44.18 98.83,44.45 90.42,44.45 89.03,43.05 85.98,43.05 v2(85.81,43.22)
C2_RX2-: length 22.6
  TOP w0.155: U5.1 101.99,43.8 102.57,43.8 v2(102.79,43.58) 103.01,43.8 103.4,43.8 103.46,43.74 CN5.A10 ; v2(85.81,42.51) 85.65,42.67 85.37,42.67 84.93,42.22 83.48,42.22 U8.E6
  L3_SIG w0.13: v2(85.81,42.51) 85.98,42.67 89.18,42.67 90.58,44.07 98.67,44.07 98.95,43.8 102.58,43.8 v2(102.79,43.58)
C2_SBU1: length 27.8
  TOP w0.127: v1(102.74,57.91) 102.23,57.4 100.46,57.4 99.86,56.81 U16.1 ; v1(102.62,51.05) 103.38,50.29 103.38,48.51 SB41.1 102.36,47.07 101.9,46.61 100.48,46.61 100.28,46.81 99.87,46.81 99.57,46.51 99.57,46 99.98,45.59 99.98,44.84 99.99,44.84 99.99,44.49 100.23,44.25 100.23,43.38 100.48,43.13 102.33,43.13 102.53,42.93 103.02,42.93 103.21,42.74 CN5.A8
  BOTTOM w0.127: D2.3 102.68,50.99 v1(102.62,51.05) 102.62,51.69 101.98,52.32 101.98,57.15 v1(102.74,57.91)
C2_SBU2: length 42.5
  TOP w0.127: v1(101.73,57.91) 101.6,57.78 100.3,57.78 99.48,56.97 99.48,56.93 99.46,56.92 U16.2 ; CN5.B8 106.13,41.19 106.71,40.61 106.71,39.22 105.99,38.51 104.32,38.51 102.57,36.75 97.61,36.75 97.03,37.34 97.03,43.21 98.04,44.22 98.96,44.22 99.46,44.73 99.46,45.57 99.19,45.84 99.19,46.67 99.89,47.37 100.97,47.37 ; SB42.1 100.08,48.39 v1(100.08,50.42)
  BOTTOM w0.127: D2.1 100.78,49.72 v1(100.08,50.42) 100.08,52.5 101.47,53.9 101.47,57.66 v1(101.73,57.91)
C2_TX1+: length 22.9
  TOP w0.155: v2(87.25,41.06) 87.08,41.22 83.48,41.22 U8.G6 ; CN5.A2 103.39,39.74 103.33,39.8 102.96,39.8 v2(102.74,39.58) 102.52,39.8 101.99,39.8 U11.4
  L3_SIG w0.13: v2(87.25,41.06) 87.41,41.22 94.76,41.22 97.05,38.94 99.32,38.94 100.18,39.8 102.53,39.8 v2(102.74,39.58)
C2_TX1-: length 22.9
  TOP w0.155: U8.F6 83.48,41.6 87.08,41.6 v2(87.25,41.77) ; CN5.A3 103.36,40.24 103.3,40.18 102.96,40.18 v2(102.74,40.39) 102.53,40.18 101.99,40.18 U11.5
  L3_SIG w0.13: v2(102.74,40.39) 102.53,40.18 100.02,40.18 99.16,39.32 97.21,39.32 94.92,41.61 87.41,41.61 v2(87.25,41.77)
C2_TX2+: length 41.1
  TOP w0.155: U8.C6 83.48,43.22 83.89,43.22 84.74,44.07 85.72,44.07 86.2,44.54 87.66,44.54 v2(87.87,44.32) ; U5.5 102.01,45.67 102.94,45.67 103.59,46.32 104.31,46.32 v2(104.44,46.45)
  L3_SIG w0.13: v2(87.87,44.32) 87.66,44.54 87.12,44.54 86.77,44.89 86.77,46.64 87.12,46.99 99.16,46.99 99.49,47.32 100.71,47.32 101.72,46.31 104.31,46.31 v2(104.44,46.45)
  BOTTOM w0.155: v2(104.44,46.45) 104.44,46.3 104.24,46.1 103.97,46.1 103.78,46.28 103.78,46.69 104.39,47.29 104.69,47.29 104.9,47.09 105.21,47.09 105.41,47.29 105.72,47.29 105.92,47.09 106.23,47.09 106.44,47.29 106.75,47.29 107.26,46.78 107.26,44.91 107.14,44.78 106.98,44.78 106.41,45.35 106.21,45.35 106.02,45.16 106.02,44.91 106.55,44.37 106.55,44.07 106.45,43.97 106.09,43.97 CN5.B2
C2_TX2-: length 41.2
  TOP w0.155: U5.4 101.98,45.29 103.1,45.29 103.75,45.94 104.15,45.94 v2(104.44,45.64) ; U8.B6 83.48,43.6 83.74,43.6 84.58,44.45 85.57,44.45 86.04,44.92 87.66,44.92 v2(87.87,45.14)
  L3_SIG w0.13: v2(104.44,45.64) 104.15,45.93 101.56,45.93 100.55,46.94 99.65,46.94 99.32,46.61 95.31,46.61 95.08,46.38 94.82,46.38 94.59,46.61 94.33,46.61 94.1,46.38 93.84,46.38 93.61,46.61 92.55,46.61 92.35,46.41 92.09,46.41 91.89,46.61 91.63,46.61 91.43,46.41 91.17,46.41 90.96,46.61 90.7,46.61 90.5,46.41 90.24,46.41 90.04,46.61 89.78,46.61 89.58,46.41 89.32,46.41 89.11,46.61 88.86,46.61 88.65,46.41 88.39,46.41 88.19,46.61 87.28,46.61 87.15,46.48 87.15,45.05 87.28,44.92 87.66,44.92 v2(87.87,45.14)
  BOTTOM w0.155: v2(104.44,45.64) 104.36,45.72 103.81,45.72 103.4,46.13 103.4,46.84 104.24,47.68 106.91,47.68 107.65,46.94 107.65,44.62 106.61,43.59 CN5.B3
CON1_D+: length 55.1
  L3_SIG w0.13: v1(41.76,37.96) 41.97,37.75 41.97,35.21 43.91,33.27 53.69,33.27 55.5,31.47 55.5,11.21 52.67,8.38 46.26,8.38 45.02,7.14 45.02,4.96 44.89,4.83 CN10.1
  BOTTOM w0.155: v1(41.76,37.96) 41.97,38.18 41.97,38.52 SB61.1
CON1_D-: length 55.1
  L3_SIG w0.13: CN10.2 45.53,4.83 45.4,4.96 45.4,6.99 46.42,8 52.83,8 55.88,11.05 55.88,31.62 53.85,33.66 44.07,33.66 42.35,35.37 42.35,37.75 v1(42.57,37.96)
  BOTTOM w0.155: v1(42.57,37.96) 42.35,38.18 42.35,38.52 SB60.1
CON2_D+: length 79.6
  TOP w0.155: v1(84.41,51.85) 84.63,51.64 85.14,51.64 SB67.2
  L3_SIG w0.13: CN10.3 49.97,4.83 50.1,4.96 50.1,5.81 50.9,6.6 53.09,6.6 56.92,10.44 56.92,33.43 58.72,35.23 81.08,35.23 82.5,36.65 82.5,39.99 83.64,41.13 83.64,45.74 82.68,46.71 82.68,51.08 83.23,51.64 84.2,51.64 v1(84.41,51.85)
CON2_D-: length 79.6
  TOP w0.155: SB66.2 85.12,51.26 84.63,51.26 v1(84.41,51.04)
  L3_SIG w0.13: v1(84.41,51.04) 84.2,51.26 83.39,51.26 83.06,50.93 83.06,50.34 83.31,50.09 83.31,49.83 83.06,49.57 83.06,49.32 83.31,49.06 83.31,48.8 83.06,48.55 83.06,48.29 83.31,48.04 83.31,47.78 83.06,47.52 83.06,46.86 84.02,45.9 84.02,40.97 82.88,39.83 82.88,36.49 81.23,34.85 58.88,34.85 57.3,33.27 57.3,10.28 53.24,6.22 51.05,6.22 50.48,5.65 50.48,4.96 50.61,4.83 CN10.4
CS: length 3.9
  TOP w0.127: R18.1 70.62,44.57 v1(69.85,44.57) U6.17
  BOTTOM w0.127: R18.1 70.62,44.57 v1(69.85,44.57)
DCDC_EN: length 58.7
  TOP w0.508: R3.1 R6.2 v1(83.31,19.94)
  BOTTOM w0.127: v1(83.31,19.94) 78.49,19.94 74.17,15.62 60.33,15.62 58.42,17.53 49.91,17.53 48.13,15.75 48.13,13.34 47.88,13.08 R82.2 46.35,12.7 46.35,11.41 U7.3
  BOTTOM w0.508: v1(83.31,19.94) 83.57,19.94 86.49,17.02 89.94,17.02 90.68,17.75 SB26.1 SB23.2
DISCHARGE_1: length 18.4
  TOP w0.508: SB35.1 33.15,17.4 34.04,18.29 34.04,22.73 v1(34.42,23.11)
  L3_SIG w0.508: v1(34.42,23.11) 34.42,23.5 34.67,23.75 37.47,23.75 38.1,24.38 38.1,28.45 CN9.8
DISCHARGE_2: length 4.3
  BOTTOM w0.508: SB36.1 36.65,28.02 CN9.9
DP_PWR_SINK: length 11.7
  TOP w0.254: TP4.1 15.62,45.97 15.62,43.23 14.99,42.6 CN6.20
  BOTTOM w0.254: SB43.2 15.62,45.97 TP4.1
DP_PWR_SOURCE: length 8.6
  TOP w0.254: CN2.20 70.54,59.38 71.75,58.17 73.79,58.17 TP1.1
  BOTTOM w0.254: TP1.1 74.8,56.9 73.53,56.9 SB40.1
DPEQ0_A1: length 3.8
  TOP w0.127: U13.14 v1(23.04,37.41)
  BOTTOM w0.127: v1(23.04,37.41) 22.79,37.41 R100.2 R98.1
DPEQ1: length 6.1
  TOP w0.127: U13.2 27.29,40.62 28.32,41.66 28.51,41.66 29.15,42.29 29.46,42.29 R21.2 R16.1
EQ0: length 4
  TOP w0.127: v1(29.58,39.51) 29.57,39.5 29.54,39.5 28.65,38.61 U13.38
  BOTTOM w0.127: v1(29.58,39.51) 29.72,39.37 R97.2 R99.1
EQ1: length 3.8
  TOP w0.127: U13.35 v2(29.64,37.41)
  BOTTOM w0.127: v2(29.64,37.41) 29.9,37.41 R102.1 R108.2
FRS_TX1: length 7.1
  TOP w0.508: CN8.8 97.28,29.21 v1(94.74,29.21)
  BOTTOM w0.508: v1(94.74,29.21) 94.61,29.21 93.85,28.45 R113.1 92.35,28.32 T12.1
FRS_TX2: length 6.6
  TOP w0.508: CN8.9 97.41,26.8 R35.1 93.67,26.61 T4.1
GAIN: length 4.8
  TOP w0.127: R24.2 59.44,42.55 59.56,42.55 v1(59.69,42.67) 59.82,42.67 60.71,43.57 U6.36
  BOTTOM w0.127: R24.2 59.44,42.55 59.56,42.55 v1(59.69,42.67)
HPD_SOURCE: length 62.9
  TOP w0.127: U3.4 71.49,55.25 71.91,54.84 v1(71.91,54.56) ; v1(69.98,57.53) 69.54,57.97 CN2.18
  BOTTOM w0.127: R81.1 70.6,59.56 69.98,58.94 v1(69.98,57.53) 69.98,56.9 71.91,54.97 v1(71.91,54.56) 71.91,51.97 70.87,50.93 48.9,50.93 45.85,47.88 45.85,36.83 42.42,33.4 39.24,33.4 38.61,32.77 CN9.7
HPDIN: length 125.7
  TOP w0.127: v1(16.26,39.62) 16.52,39.89 U9.4 ; CN6.18 11.75,41.6 11.56,41.4 v1(11.43,41.4) ; SB20.2 v1(24.89,28.83)
  L3_SIG w0.102: v1(54.48,40.64) 53.98,40.13 49.91,40.13 49.02,41.02 48.26,41.02 47.5,40.26 40.64,40.26 36.83,44.07 35.94,44.07 v1(34.67,42.8)
  BOTTOM w0.127: v1(34.67,42.8) 34.67,42.24 34.75,42.16 34.75,34.49 32,31.75 30.99,31.75 30.73,32 SB48.2 28.07,32 v1(24.89,28.83) 24.26,28.83 23.7,29.39 19.25,29.39 14.81,33.83 14.81,38.18 v1(16.26,39.62) 15.95,39.93 15.82,39.93 R96.1 14.35,41.4 v1(11.43,41.4) ; CN8.11 97.03,22.61 95.38,24.26 93.09,24.26 92.84,24.51 92.84,25.15 92.46,25.53 87.66,25.53 84.58,28.61 84.58,32.26 83.69,33.15 72.01,33.15 69.98,35.18 59.44,35.18 54.48,40.13 v1(54.48,40.64)
I2C_EN_1: length 4.6
  TOP w0.127: v1(22.91,34.92) 22.91,35.36 23.77,36.21 U13.17
  BOTTOM w0.127: v1(22.91,34.92) 22.73,34.92 R109.1 R103.2
I2C_EN_2: length 4.3
  TOP w0.127: U6.16 69.6,44.07 v1(69.91,43.75) 70.17,43.75 R23.1
  BOTTOM w0.127: R23.1 70.17,43.75 v1(69.91,43.75)
I2C_SCL: length 88.8
  TOP w0.127: v1(80.52,37.21) 77.98,37.21 76.45,38.73 76.45,40.51 74.55,42.42 v1(74.3,42.42) 73.03,42.42 SB7.1 ; v3(81.92,39.37) 82.42,39.87 U8.J4 ; SB18.2 v1(22.1,28.78)
  L3_SIG w0.102: v1(74.3,42.42) 70.36,42.42 69.22,43.56 64.01,43.56 60.58,40.13 60.15,40.13 59.5,40.79 57.43,40.79 56.39,39.75 39.5,39.75 CN9.3
  BOTTOM w0.127: v1(22.1,28.78) 22.1,28.7 22.89,27.91 26.39,27.91 28.32,29.84 30.35,29.84 31.11,29.08 32.51,29.08 33.02,29.59 33.02,31.42 35.51,33.91 37.09,33.91 37.9,34.72 37.9,41.35 CN9.3 ; v3(81.92,39.37) 81.92,38.61 v1(80.52,37.21) R107.1
I2C_SDA: length 83.6
  TOP w0.127: v1(81.92,37.21) 81.41,36.7 77.72,36.7 75.95,38.48 75.95,40.26 74.42,41.78 v1(73.79,41.78) SB10.1 ; SB19.2 v1(23.5,28.78) ; U8.H4 82.42,41.08 v3(82.37,41.12)
  L3_SIG w0.102: v1(73.79,41.78) 73.51,42.06 69.95,42.06 68.83,43.18 64.26,43.18 60.71,39.62 59.94,39.62 59.29,40.28 57.64,40.28 56.73,39.37 38.73,39.37 37.72,40.39 CN9.4
  BOTTOM w0.127: R106.1 v1(81.92,37.21) 82.42,37.72 82.42,41.07 v3(82.37,41.12) ; v1(23.5,28.78) 23.98,28.3 26.14,28.3 28.07,30.23 30.1,30.23 31.11,31.24 32.28,31.24 35.33,34.29 36.93,34.29 37.52,34.87 37.52,39.19 CN9.4
ISENSE_1: length 30.1
  TOP w0.381: U23.6 21.45,5.6 21.21,5.84 v1(20.7,5.84)
  BOTTOM w0.508: v1(20.7,5.84) 20.7,8.76 22.61,10.67 22.61,16.89 23.37,17.65 33.27,17.65 35.05,19.43 35.05,21.34 CN9.11
ISENSE_2: length 12.2
  TOP w0.356: U24.6 43.08,11.21 43.05,11.18
  TOP w0.508: 43.05,11.18 38.99,11.18 38.1,12.06 38.1,15.75 CN9.13
L0_N_1: length 10.9
  TOP w0.13: v2(19.51,40.92) 19.67,41.08 20.13,41.08 C24.1 ; CN6.10 14.36,37.6 14.64,37.88 14.64,37.89 14.66,37.9 16.32,37.9 v2(16.48,37.73) 16.65,37.9 17.13,37.9 U12.2
  BOTTOM w0.13: v2(16.48,37.73) 16.65,37.9 17.08,37.9 17.68,38.49 17.68,39.95 18.81,41.08 19.34,41.08 v2(19.51,40.92)
L0_N_2: length 12.4
  TOP w0.13: CN2.3 62.04,59.16 61.7,58.82 61.7,57.57 v2(61.84,57.43) ; U1.2 61.73,55.25 61.67,55.19 61.67,54.24 v2(61.84,54.08) 61.67,53.91 61.67,53.4 60.91,52.64 60.91,50.98 C6.2
  BOTTOM w0.13: v2(61.84,57.43) 61.67,57.27 61.67,54.24 v2(61.84,54.08)
L0_P_1: length 10.9
  TOP w0.13: CN6.12 14.36,38.6 14.53,38.43 14.53,38.43 14.64,38.32 14.64,38.31 14.68,38.28 16.32,38.28 v2(16.48,38.44) 16.65,38.28 17.13,38.28 U12.1 ; C23.1 20.13,41.47 19.67,41.47 v2(19.51,41.63)
  BOTTOM w0.13: v2(19.51,41.63) 19.34,41.47 18.65,41.47 17.3,40.11 17.3,38.65 16.92,38.28 16.65,38.28 v2(16.48,38.44)
L0_P_2: length 12.4
  TOP w0.13: C5.2 60.53,51 60.53,52.8 61.29,53.56 61.29,53.91 v2(61.12,54.08) 61.29,54.24 61.29,55.3 61.23,55.36 U1.1 ; CN2.1 61.04,59.13 61.32,58.85 61.32,57.62 v2(61.12,57.43)
  BOTTOM w0.13: v2(61.12,57.43) 61.29,57.27 61.29,54.24 v2(61.12,54.08)
L1_N_1: length 9.9
  TOP w0.13: C36.1 20.13,38.54 19.67,38.54 v2(19.51,38.38) ; U12.5 17.13,36.4 16.65,36.4 v2(16.48,36.23) 16.32,36.4 14.76,36.4 14.46,36.1 CN6.7
  BOTTOM w0.13: v2(19.51,38.38) 19.34,38.54 18.94,38.54 18.72,38.33 18.72,37.84 17.28,36.4 16.65,36.4 v2(16.48,36.23)
L1_N_2: length 12.2
  TOP w0.13: v2(63.34,57.43) 63.2,57.57 63.2,58.9 63.54,59.25 CN2.6 ; U1.5 63.23,54.99 63.17,54.93 63.17,54.24 v2(63.34,54.08) 63.17,53.91 63.17,52.17 63.44,51.9 63.44,50.99 C8.2
  BOTTOM w0.13: v2(63.34,54.08) 63.17,54.24 63.17,57.27 v2(63.34,57.43)
L1_P_1: length 9.9
  TOP w0.13: v2(19.51,39.09) 19.67,38.93 20.13,38.93 C25.1 ; CN6.9 14.46,37.1 14.78,36.78 16.32,36.78 v2(16.48,36.94) 16.65,36.78 17.13,36.78 U12.4
  BOTTOM w0.13: v2(19.51,39.09) 19.34,38.93 18.78,38.93 18.34,38.49 18.34,38 17.12,36.78 16.65,36.78 v2(16.48,36.94)
L1_P_2: length 12.2
  TOP w0.13: U1.4 62.73,54.99 62.79,54.93 62.79,54.24 v2(62.62,54.08) 62.79,53.91 62.79,52.01 63.06,51.75 63.06,50.99 C7.2 ; CN2.4 62.54,59.21 62.81,58.93 62.81,57.62 v2(62.62,57.43)
  BOTTOM w0.13: v2(62.62,54.08) 62.79,54.24 62.79,57.27 v2(62.62,57.43)
L2_N_1: length 9.2
  TOP w0.13: C42.1 20.13,36 19.67,36 v2(19.51,35.84) ; CN6.4 14.4,34.6 14.68,34.87 16.29,34.87 v2(16.48,34.68) 16.65,34.85 17.13,34.85 U15.2
  BOTTOM w0.13: v2(16.48,34.68) 16.65,34.85 17.63,34.85 18.79,36 19.34,36 v2(19.51,35.84)
L2_N_2: length 12.6
  TOP w0.13: v2(64.88,57.43) 64.72,57.6 64.72,58.93 65.04,59.25 CN2.9 ; C10.2 65.98,50.99 65.98,51.68 64.72,52.93 64.72,53.91 v2(64.88,54.08) 64.72,54.24 64.72,55.32 64.78,55.38 U2.2
  BOTTOM w0.13: v2(64.88,57.43) 64.72,57.27 64.72,54.24 v2(64.88,54.08)
L2_P_1: length 9.2
  TOP w0.13: C39.1 20.13,36.39 19.67,36.39 v2(19.51,36.55) ; CN6.6 14.39,35.6 14.73,35.26 16.34,35.26 v2(16.48,35.4) 16.65,35.23 17.13,35.23 U15.1
  BOTTOM w0.13: v2(16.48,35.4) 16.65,35.23 17.48,35.23 18.63,36.39 19.34,36.39 v2(19.51,36.55)
L2_P_2: length 12.6
  TOP w0.13: U2.1 64.28,55.36 64.34,55.3 64.34,54.24 v2(64.17,54.08) 64.34,53.91 64.34,52.78 65.6,51.52 65.6,50.99 C9.2 ; v2(64.17,57.43) 64.34,57.6 64.34,58.95 64.04,59.25 CN2.7
  BOTTOM w0.13: v2(64.17,57.43) 64.34,57.27 64.34,54.24 v2(64.17,54.08)
L3_N_1: length 8.8
  TOP w0.13: C46.1 20.13,33.46 19.67,33.46 v2(19.51,33.3) ; CN6.1 14.38,33.1 14.66,33.38 16.29,33.38 v2(16.48,33.18) 16.65,33.35 17.13,33.35 U15.5
  BOTTOM w0.13: v2(16.48,33.18) 16.65,33.35 17.76,33.35 17.87,33.46 19.34,33.46 v2(19.51,33.3)
L3_N_2: length 13.4
  TOP w0.13: v2(66.38,57.43) 66.22,57.6 66.22,58.93 66.54,59.25 CN2.12 ; U2.5 66.28,55.36 66.22,55.3 66.22,54.24 v2(66.38,54.08) 66.22,53.91 66.22,53.47 66.88,52.81 67.49,52.81 68.52,51.78 68.52,50.99 C12.2
  BOTTOM w0.13: v2(66.38,54.08) 66.22,54.24 66.22,57.27 v2(66.38,57.43)
L3_P_1: length 8.8
  TOP w0.13: U15.4 17.13,33.73 16.65,33.73 v2(16.48,33.9) 16.34,33.76 14.76,33.76 14.42,34.1 CN6.3 ; C44.1 20.13,33.85 19.67,33.85 v2(19.51,34.01)
  BOTTOM w0.13: v2(16.48,33.9) 16.65,33.73 17.6,33.73 17.72,33.85 19.34,33.85 v2(19.51,34.01)
L3_P_2: length 13.4
  TOP w0.13: CN2.10 65.54,59.23 65.84,58.93 65.84,57.6 v2(65.67,57.43) ; U2.4 65.78,55.38 65.84,55.32 65.84,54.24 v2(65.67,54.08) 65.84,53.91 65.84,53.31 66.73,52.43 67.33,52.43 68.14,51.62 68.14,50.99 C11.2
  BOTTOM w0.13: v2(65.67,54.08) 65.84,54.24 65.84,57.27 v2(65.67,57.43)
LOCAL_PWR1: length 39.4
  TOP w0.356: U23.4 22.75,5.86 23.37,6.48
  TOP w0.381: T6.8 24.68,24.81 ; T6.6 24.69,26.11 ; T6.7 24.69,25.46 ; T6.5 24.68,26.76
  TOP w0.508: 25.63,20.52 R49.1 ; R49.1 25.63,23.42 ; R49.1 26.31,21.97 ; R49.1 24.94,21.97 ; 25.63,17.35 R56.1 ; R56.1 25.63,20.24 ; R56.1 26.31,18.8 ; R56.1 24.94,18.8 ; R52.1 26.31,12.45 ; R52.1 25.63,11 ; R52.1 24.94,12.45 ; R52.1 25.63,13.89 ; 24.94,15.62 R47.1 ; R47.1 25.63,17.07 ; R47.1 25.63,14.17 ; R47.1 26.31,15.62 ; TP9.1 24.69,23.5 ; TP9.1 23.75,22.55 ; TP9.1 22.81,23.5 ; TP9.1 23.75,24.44 ; 25.4,6.68 R69.1 ; R69.1 24.08,8.64 ; R69.1 26.72,8.64 ; R69.1 25.4,10.59
  BOTTOM w0.381: T10.6 28.63,15.31 ; T10.7 29.28,15.31
  BOTTOM w0.508: D3.1 33.53,13.96 ; D3.1 31.5,13.96 ; D3.1 32.51,15.15 ; 27.6,14.52 T10.5 27.98,15.19 ; 29.93,15.19 T10.8 30.31,14.52
  vias: v1(23.75,16.51) v1(23.75,14.61) v1(24.51,16.51) v1(24.49,14.61)
LOCAL_PWR2: length 33.1
  TOP w0.356: U24.4 44.97,11.95 45.34,12.32 45.85,12.32
  TOP w0.508: 47.47,18.8 R48.1 ; R48.1 48.16,17.35 ; R48.1 48.84,18.8 ; R48.1 48.16,20.24 ; 48.03,23.95 R59.1 ; R59.1 48.03,26.85 ; R59.1 47.35,25.4 ; R59.1 48.72,25.4 ; R55.1 48.72,28.7 ; R55.1 48.03,27.25 ; R55.1 47.35,28.7 ; R55.1 48.03,30.15 ; 51.74,14.5 JP5.3 ; JP5.3 51.74,16.38 ; JP5.3 52.68,15.44 ; JP5.3 50.8,15.44 ; R70.1 48.82,14.48 ; R70.1 47.5,16.43 ; R70.1 47.5,12.52 ; R70.1 46.18,14.48 ; 29.72,3.34 CN12.1 ; CN12.1 30.7,4.32 ; CN12.1 29.72,5.3 ; CN12.1 28.74,4.32 ; R50.1 48.84,22.1 ; R50.1 47.47,22.1 ; R50.1 48.16,23.55 ; R50.1 48.16,20.65
NETC1_1: length 24.6
  TOP w0.508: 34.04,60.38 CN3.2 ; CN3.2 35.03,61.67 ; CN3.2 34.04,62.95 ; CN3.2 33.05,61.67 ; C1.1 42.62,65.28 ; C1.1 42.04,64.66 ; C1.1 41.45,65.28 ; 28.44,60.38 CN3.5 ; CN3.5 27.45,61.67 ; CN3.5 28.44,62.95 ; CN3.5 29.43,61.67 ; Z1.2 40.64,64.14 ; Z1.2 39.62,62.96 ; Z1.2 39.62,65.32 ; Z1.2 38.61,64.14
  TOP w1.016: L1.1 49.11,68.16 46.1,65.15 43.43,65.15
NETC1_2: length 19.9
  TOP w0.508: 38.61,67.94 Z1.1 ; Z1.1 40.64,67.94 ; Z1.1 39.62,69.12 ; Z1.1 39.62,66.76 ; 31.24,63.62 CN3.1 ; CN3.1 31.24,65.61 ; CN3.1 29.7,64.62 ; CN3.1 32.78,64.62 ; 41.45,66.8 C1.2 ; C1.2 42.04,67.42 ; C1.2 42.62,66.8 ; CN3.3 31.24,69.36 ; CN3.3 31.24,67.37 ; CN3.3 32.78,68.37 ; CN3.3 29.7,68.37 ; 47.75,68.33 47.59,68.16 L1.2 ; L1.2 46.52,69.33 ; L1.2 45.35,68.16
NETC3_1: length 5
  BOTTOM w0.508: U28.3 26.43,20.7 C3.1 R64.1 R119.2
NETC4_1: length 10
  TOP w0.381: T6.2 29.52,25.46 ; T7.3 45.28,32.95 ; T6.3 30.03,26.11 ; T6.1 29.68,24.81
  TOP w0.508: 42.09,33.15 R42.2 ; R42.2 42.67,33.72 ; R42.2 43.26,33.15 ; 43.87,33.15 C4.1 ; C4.1 44.45,33.77 ; C4.1 45.03,33.15 ; T7.1 45.25,34.25 ; T7.2 45.27,33.6
NETC4_2: length 20.9
  TOP w0.381: T7.4 45.89,32.3 45.21,31.62 44.45,31.62 ; T6.4 30.19,26.76 R41.2
  TOP w0.508: 42.67,31.62 v1(43.56,31.62) 44.45,31.62 ; R41.2 v1(31.11,27.69)
  BOTTOM w0.508: v1(43.56,31.62) 40.01,31.62 37.34,28.96 35.56,28.96 34.29,27.69 v1(31.11,27.69)
NETC5_1: length 3.8
  TOP w0.13: C5.1 60.52,48.58 60.52,47.91 60.93,47.5 61.59,47.5 62.08,47.01 62.08,46.56 U6.31
NETC6_1: length 3.8
  TOP w0.13: C6.1 60.9,48.58 60.9,48.07 61.09,47.88 61.75,47.88 62.46,47.17 62.46,46.56 U6.30
NETC7_1: length 2.9
  TOP w0.13: C7.1 63.06,48.58 63.06,48.17 63.58,47.64 63.58,46.56 U6.28
NETC8_1: length 2.9
  TOP w0.13: C8.1 63.44,48.58 63.44,48.32 63.96,47.8 63.96,46.56 U6.27
NETC9_1: length 2.7
  TOP w0.13: U6.24 65.58,46.56 65.58,48.59 C9.1
NETC10_1: length 2.7
  TOP w0.13: U6.23 65.96,46.56 65.96,48.56 C10.1
NETC11_1: length 3.2
  TOP w0.13: U6.21 67.08,46.56 67.08,47.3 68.14,48.35 68.14,48.58 C11.1
NETC12_1: length 3.2
  TOP w0.13: U6.20 67.46,46.56 67.46,47.14 68.52,48.2 68.52,48.58 C12.1
NETC13_1: length 16.1
  TOP w0.13: U8.A3 81.98,44.22 81.98,45.78 82.17,45.97 82.17,47.09 81.88,47.37 71.25,47.37 70.68,47.94 70.68,48.58 C13.1
NETC14_1: length 16.1
  TOP w0.13: C14.1 71.06,48.58 71.06,48.1 71.4,47.75 82.04,47.75 82.55,47.24 82.55,45.82 82.36,45.63 82.36,44.22 U8.A4
NETC18_1: length 5.4
  BOTTOM w0.508: R63.1 C18.1 52.26,21.66 ; 52.26,21.66 U27.3 ; 52.26,21.66 52.26,19.62 R118.2
NETC19_2: length 3.5
  TOP w0.155: U13.8 24.89,40.11 24.89,40.39 24.32,40.96 24.32,42.74 C19.2
NETC20_2: length 3.5
  TOP w0.155: U13.7 25.27,40.13 25.27,40.54 24.7,41.12 24.7,42.74 C20.2
NETC21_2: length 3.6
  TOP w0.155: U13.5 26.09,40.11 26.09,40.11 26.09,41.62 26.99,42.51 26.99,42.74 C21.2
NETC22_2: length 3.6
  TOP w0.155: C22.2 27.37,42.74 27.37,42.35 26.47,41.46 26.47,40.13 U13.4
NETC23_2: length 3.8
  TOP w0.13: U13.9 24.38,39.4 24.26,39.4 24.13,39.53 24.13,40.26 22.92,41.47 22.54,41.47 C23.2
NETC24_2: length 3.8
  TOP w0.13: C24.2 22.54,41.08 22.77,41.08 23.75,40.1 23.75,39.37 24.1,39.02 24.38,39.02 U13.10
NETC25_2: length 2.8
  TOP w0.13: C25.2 22.58,38.89 23.09,38.89 23.77,38.2 24.38,38.2 U13.12
NETC26_1: length 2.8
  TOP w0.155: C26.1 30.02,38.91 29.61,38.91 28.91,38.21 U13.37
NETC27_1: length 30.8
  TOP w0.13: C27.1 60.64,37.27 60.64,36.8 v2(60.43,36.59) ; v2(80.81,46.07) 80.98,45.91 80.98,44.22 U8.A1
  L3_SIG w0.104: v2(80.81,46.07) 80.98,45.91 80.98,45.6 80.63,45.25 76.5,45.25 74.93,43.69 74.93,41.78 74.42,41.27 68.83,41.27 68.2,41.91 64.1,41.91 63.25,41.05 63.25,40.16 60.64,37.56 60.64,36.8 v2(60.43,36.59)
NETC27_2: length 3.5
  TOP w0.13: C27.2 60.64,39.69 60.64,40.2 61.21,40.77 61.72,40.77 62.08,41.13 62.08,41.58 U6.1
NETC28_1: length 30.8
  TOP w0.13: v2(81.52,46.07) 81.36,45.91 81.36,44.22 U8.A2 ; C28.1 61.02,37.27 61.02,36.8 v2(61.24,36.59)
  L3_SIG w0.104: v2(61.24,36.59) 61.02,36.8 61.02,37.4 63.63,40.01 63.63,40.89 64.26,41.53 68.04,41.53 68.68,40.89 74.58,40.89 75.31,41.63 75.31,43.53 76.65,44.87 80.79,44.87 81.36,45.44 81.36,45.91 v2(81.52,46.07)
NETC28_2: length 3.5
  TOP w0.13: U6.2 62.46,41.58 62.46,40.97 61.87,40.39 61.37,40.39 61.02,40.04 61.02,39.7 61.47,39.26 C28.2
NETC29_1: length 22.2
  TOP w0.13: U8.F1 80.86,41.6 80.2,41.6 79.14,41.6 v2(78.97,41.77) ; v2(62.97,36.59) 63.18,36.8 63.18,37.27 C29.1
  L3_SIG w0.104: v2(62.97,36.59) 63.18,36.8 63.18,37.79 65.65,40.26 75.71,40.26 77.06,41.6 78.81,41.6 v2(78.97,41.77)
NETC29_2: length 2.8
  TOP w0.13: C29.2 63.18,39.69 63.18,40.1 63.58,40.5 63.58,41.58 U6.4
NETC30_1: length 22.1
  TOP w0.13: C30.1 63.56,37.27 63.56,36.8 v2(63.78,36.59) ; U8.G1 80.86,41.22 80.2,41.22 79.14,41.22 v2(78.97,41.06)
  L3_SIG w0.104: v2(63.78,36.59) 63.56,36.8 63.56,37.63 65.81,39.88 66.18,39.88 66.41,39.65 66.62,39.65 66.85,39.88 67.05,39.88 67.28,39.65 67.49,39.65 67.72,39.88 67.93,39.88 68.16,39.65 68.37,39.65 68.59,39.88 75.87,39.88 77.21,41.22 78.81,41.22 v2(78.97,41.06)
NETC30_2: length 2.8
  TOP w0.13: U6.5 63.96,41.58 63.96,40.34 63.56,39.94 63.56,39.69 C30.2
NETC31_1: length 19.3
  TOP w0.13: v2(77.78,39.92) 77.95,39.75 79.57,39.75 80.43,40.6 80.86,40.6 U8.H1 ; C31.1 65.72,37.27 65.72,36.8 v2(65.51,36.59)
  L3_SIG w0.104: v2(77.78,39.92) 77.62,39.75 76.96,39.75 76.23,39.01 66.85,39.01 65.72,37.88 65.72,36.8 v2(65.51,36.59)
NETC31_2: length 2.7
  TOP w0.13: U6.8 65.58,41.58 65.58,40.66 65.72,40.52 65.72,39.69 C31.2
NETC32_1: length 19.2
  TOP w0.13: C32.1 66.1,37.27 66.1,36.8 v2(66.32,36.59) ; v2(77.78,39.2) 77.95,39.37 79.73,39.37 80.58,40.22 80.86,40.22 U8.J1
  L3_SIG w0.104: v2(77.78,39.2) 77.62,39.37 77.12,39.37 76.38,38.63 69.79,38.63 69.57,38.4 69.36,38.4 69.13,38.63 68.92,38.63 68.69,38.4 68.48,38.4 68.26,38.63 68.05,38.63 67.82,38.4 67.61,38.4 67.38,38.63 67.01,38.63 66.1,37.73 66.1,36.8 v2(66.32,36.59)
NETC32_2: length 2.7
  TOP w0.13: C32.2 66.1,39.69 66.1,40.68 65.96,40.82 65.96,41.58 U6.9
NETC33_1: length 22.3
  TOP w0.13: v2(68.05,36.59) 68.26,36.8 68.26,37.27 C33.1 ; v2(79.05,43.34) 79.22,43.51 79.52,43.51 79.81,43.22 80.86,43.22 U8.C1
  L3_SIG w0.104: v2(79.05,43.34) 79.22,43.5 79.73,43.5 80.06,43.17 80.06,42.94 79.83,42.71 79.83,42.51 80.06,42.28 80.06,42.07 79.83,41.84 79.83,41.63 80.06,41.4 80.06,41.2 79.83,40.97 79.83,40.76 80.06,40.53 80.06,39.6 78.12,37.67 68.73,37.67 68.26,37.2 68.26,36.8 v2(68.05,36.59)
NETC33_2: length 3.1
  TOP w0.13: U6.11 67.08,41.58 67.08,41.1 68.26,39.92 68.26,39.69 C33.2
NETC34_1: length 22.4
  TOP w0.13: U8.B1 80.86,43.6 79.97,43.6 79.68,43.89 79.21,43.89 v2(79.05,44.05) ; C34.1 68.64,37.27 68.64,36.8 v2(68.86,36.59)
  L3_SIG w0.104: v2(79.05,44.05) 79.22,43.88 79.89,43.88 80.44,43.33 80.44,39.45 78.28,37.29 68.89,37.29 68.64,37.04 68.64,36.8 v2(68.86,36.59)
NETC34_2: length 3.1
  TOP w0.13: U6.12 67.46,41.58 67.46,41.26 68.64,40.07 68.64,39.69 C34.2
NETC36_2: length 2.7
  TOP w0.13: C36.2 22.5,38.51 22.93,38.51 23.62,37.82 24.38,37.82 U13.13
NETC37_1: length 2.8
  TOP w0.155: C37.1 30.05,38.53 29.77,38.53 29.07,37.83 28.21,37.83 U13.36
NETC39_2: length 2.7
  TOP w0.13: U13.15 24.38,37 23.38,37 22.77,36.39 22.54,36.39 C39.2
NETC40_1: length 2.7
  TOP w0.155: C40.1 30.04,36.39 29.74,36.39 29.17,36.95 28.71,36.95 28.65,37.01 U13.34
NETC42_2: length 2.7
  TOP w0.13: C42.2 22.54,36 22.92,36 23.54,36.62 24.38,36.62 U13.16
NETC43_1: length 2.7
  TOP w0.155: U13.33 28.51,36.61 28.55,36.57 29.01,36.57 29.58,36 30.04,36 C43.1
NETC44_2: length 3.7
  TOP w0.13: U13.18 24.38,35.8 23.96,35.8 23.5,35.34 23.5,34.58 22.77,33.85 22.54,33.85 C44.2
NETC46_2: length 3.7
  TOP w0.13: C46.2 22.54,33.46 22.92,33.46 23.88,34.42 23.88,35.18 24.12,35.42 24.38,35.42 U13.19
NETC48_1: length 5.3
  TOP w0.508: C48.1 R83.1 ; C48.1 R84.2 ; C48.1 50.99,41.72 U29.3
NETC49_1: length 1.5
  TOP w0.508: 81.53,32.64 C49.1
NETC50_1: length 3.9
  TOP w0.508: U18.6 79.76,30.86 C50.1 R40.1
NETC54_1: length 2
  TOP w0.127: C54.1 16.26,20.89 15.89,21.25 15.89,21.32 15.88,21.34 U17.3
NETC55_1: length 2.3
  TOP w0.508: C55.1 v1(101.09,17.4)
  BOTTOM w0.508: v1(101.09,17.4) C55.1
NETC55_2: length 4.4
  TOP w0.508: U21.4 102.36,14.22 103.76,15.62 C58.2 C55.2
NETC56_1: length 1.3
  BOTTOM w0.508: C56.1 78.23,23.47 78.11,23.34 R110.1
NETC56_2: length 26.3
  TOP w0.508: 71.2,29.46 D4.2 ; D4.2 74.85,29.46 ; D4.2 73.03,30.78 ; D4.2 73.03,28.14 ; L2.1 68.23,34.91 ; L2.1 68.23,26.56 ; L2.1 69.62,30.73 ; L2.1 66.85,30.73 ; R111.2 77.55,30.86 ; R111.2 76.63,30.86 ; R111.2 77.09,30.4 ; 76.73,28.86 U18.8 ; U18.8 77.22,29.85 ; U18.8 77.22,27.87
  BOTTOM w0.508: C56.2 75.88,24.26 75.44,24.7 v1(75.44,28.32)
NETC57_1: length 3
  TOP w0.508: R54.1 C57.1 R61.2
NETC58_1: length 8.1
  TOP w0.508: 102.23,15.29 C58.1 ; C58.1 102.23,16.46 ; C58.1 101.61,15.88 ; 101.27,5.84 R74.1 101.85,6.41 ; 101.88,8.22 U21.5 102.36,7.23
  BOTTOM w0.508: C58.1 101.6,15.88 v1(101.09,15.37) ; R32.1 R74.1 v1(100.84,5.84)
NETC60_2: length 1.5
  TOP w0.508: R67.2 C60.2
NETC61_1: length 9.1
  TOP w0.508: 63.88,13 R67.1 ; R67.1 63.88,14.17 ; R67.1 64.45,13.59 ; R66.1 73.28,15.06 ; R66.1 73.28,13.89 ; R66.1 72.71,14.48 ; 63.88,11.48 R68.1 ; R68.1 64.45,12.06 ; R68.1 63.88,12.65 ; 72.69,13.08 73.28,13.08 73.28,13.7 ; 63.88,14.27 R65.2 64.45,14.86 ; 65.02,12.06 U22.5 66.01,12.55
NETC61_2: length 3.6
  TOP w0.508: C62.2 C61.2 72.9,11.56 72.39,12.06 U22.4
NETC62_1: length 1.4
  TOP w0.508: 74.8,13.08 R66.2
NETC72_1: length 5.5
  TOP w0.381: v1(21.84,11.56) 21.34,12.06 C72.1 21.34,13.97 U25.3
  BOTTOM w0.381: R77.1 C72.1 21.34,12.06 v1(21.84,11.56)
NETC73_1: length 5.2
  TOP w0.508: U26.3 42.73,19.87 C73.1 v1(42.67,18.8)
  BOTTOM w0.508: v1(42.67,18.8) C73.1 R78.1
NETC74_2: length 1.3
  TOP w0.508: C74.2 R74.2
NETC96_1: length 2.4
  TOP w0.127: U16.3 99.06,57.53 v1(99.31,57.78)
  BOTTOM w0.127: v1(99.31,57.78) C96.1
NETC108_1: length 1.1
  TOP w0.508: R111.1 C108.1
NETC109_1: length 2.1
  TOP w0.508: v1(82.17,31.88) 82.93,32.64
  BOTTOM w0.508: R127.1 82.3,31.88 v1(82.17,31.88)
NETC109_2: length 17
  TOP w0.508: C109.2 82.93,30.35 v1(82.55,29.97) 81.41,29.97 81.03,29.59 U18.5
  BOTTOM w0.508: v1(82.55,29.97) 82.55,29.08 R45.1 82.93,26.67 87.25,22.35 88.39,22.35 88.9,21.84 SB13.1 SB3.1
NETCN1_1: length 26.3
  L3_SIG w0.508: CN1.1 104.97,60.66 103.75,59.44 84.07,59.44 82.68,58.04 JP3.2
NETCN1_2: length 22.2
  TOP w0.155: SB64.2 91.39,51.26 91.9,51.26 92.46,51.82 92.46,54.26 91.95,54.77 91.95,59.05 93.09,60.2 101.22,60.2 101.98,60.96 101.98,62.08 CN1.2
NETCN1_3: length 22.2
  TOP w0.155: CN1.3 101.01,62.57 101.6,61.98 101.6,61.12 101.06,60.58 92.93,60.58 91.57,59.21 91.57,54.61 92.08,54.1 92.08,51.97 91.74,51.64 91.39,51.64 SB65.2
NETCN2_13: length 4.1
  TOP w0.127: CN2.13 67.04,56.91 R4.1
NETCN2_14: length 4.5
  TOP w0.127: CN2.14 67.54,57.56 68.2,56.9 68.33,56.9 R5.1
NETCN2_19: length 5.8
  TOP w0.127: CN2.19 70.04,58.61 71.37,57.28 72.39,57.28 SB1.2
NETCN4_1: length 16.9
  TOP w0.508: CN4.1 13.06,60.11 13.06,61.95 13.82,62.71 18.95,62.71 R1.1
NETCN4_2: length 39.3
  BOTTOM w0.155: 42.34,44.81 42.34,44.78 42.93,44.2 ; 42.34,44.81 SB62.1 ; 42.34,44.81 42.34,47.93 32.03,58.24 18.03,58.24 17.44,57.66 16.54,57.66 15.95,58.25 15.95,59.56 16.16,59.77 16.59,59.77 17,59.35 CN4.2
